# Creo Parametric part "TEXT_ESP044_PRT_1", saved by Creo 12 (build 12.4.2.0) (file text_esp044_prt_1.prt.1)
Units: Custom; MM, KILOGRAM, SECS

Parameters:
  PTC_WM_ITERATION = "0"
  PTC_WM_VERSION = "-.0"
  PTC_WM_LIFECYCLE_STATE = "In Work"
  PTC_WM_LIFECYCLE = "MO_CADDocument"
  PTC_WM_CREATED_BY = "Maximilian Roepper (Z0017RMS: MO)"
  PTC_WM_CREATED_ON = "18-Sep-26 11:36:42 AM"
  PTC_WM_MODIFIED_BY = "Maximilian Roepper (Z0017RMS: MO)"
  PTC_WM_MODIFIED_ON = "18-Sep-26 11:36:46 AM"
  PDMLINKNUMBER = "PDM000071455118"
  PTC_WM_NAME = "text_esp044_prt_1.prt"
  PTC_WM_NUMBER = "PDM000071455118"

Other parameters: WEIGHT, WEIGHT_FACTOR, WEIGHT_ADD, _MASS_TEMP, _DIFF_TEMP, MC_ERRORS, SUPPLIER

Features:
  1. coordinate system
  2. datum plane "PRT_YZ"
  3. datum plane "PRT_XY"
  4. datum plane "PRT_XZ"
  5. coordinate system
  6. datum axis
  7. datum axis
  8. datum axis
  9. coordinate system
  10. imported feature
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
Other named items: PRT, SIEMENS_MO, DRW_VIEW_ORG, PRT_X, PRT_Y, PRT_Z, CS0, ROUGH_GROB

Layers: 00_STD_CSYS-KSYS, 01_STD_PLANES-EBENEN, 02_STD_AXES-ACHSEN, 03_STD_CSYS-KSYS, 24_IMPORT_FEAT-IMPORT_KE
